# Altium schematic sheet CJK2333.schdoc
size 127 x 101 mm
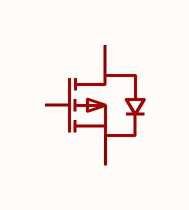
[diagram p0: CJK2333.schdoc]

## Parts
Q?  cjk2333  [SOT-23-3_L2.9-W1.6-P1.90-LS2.8-BR]  (value not drawn)

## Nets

Not connected (* = marked no-connect by the designer): Q? 1(G) 2(S) 3(D)

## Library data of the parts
Q? = cjk2333: 数量:1个P沟道;漏源电压(Vdss):12V;连续漏极电流(Id):6A;导通电阻(RDS(on)):22mΩ@4.5V;耗散功率(Pd):400mW;阈值电压(Vgs(th)):400mV;; Manufacturer: CJ(江苏长电/长晶); AddInBom: yes; ModelId: 89cb27a44ab2466697082bb9fd73a7d0; ModelName: SOT-23-3L_L2.9-W1.6-H1.1-LS2.8-P0.95; ModelTransform: 114.173,110.236,0,90,0,0,0,0,0; Number: 1个P沟道; Drain to Source Voltage: 12V; Current - Continuous Drain(Id): 6A; Pd - Power Dissipation: 400mW; Gate Threshold Voltage (Vgs(th)): 400mV; Gate Charge(Qg): 14nC@4.5V; Input Capacitance(Ciss): 1.275nF; Reverse Transfer Capacitance (Crss@Vds): 236pF; Type: P沟道; Output Capacitance(Coss): 255pF; Vgs: ±8V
